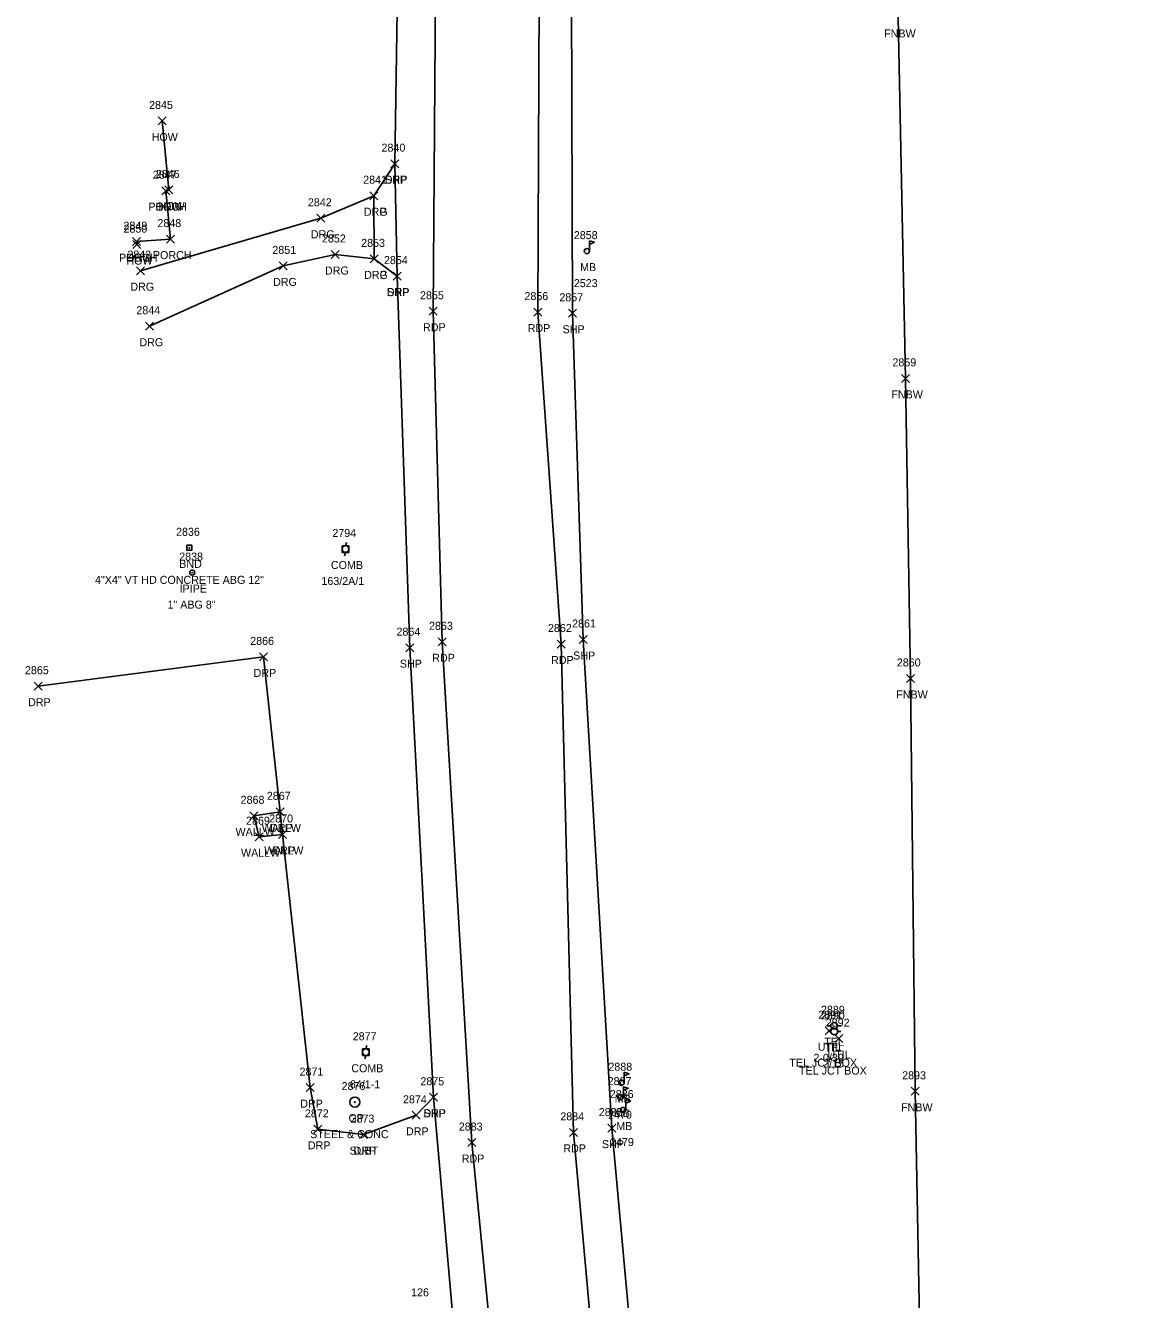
# Model space of a CAD drawing. Extents: x 1443071 to 1445292, y 614024 to 622563.
# Drawn here: x 1443923.5 to 1444198.2, y 619223.1 to 619541.5 of the extents above; entities that cross this region are included whole.
import ezdxf

# ---------------------------------------------------------------- set-up
doc = ezdxf.new("R2010")
doc.units = 0
for name, color, linetype in [('C_I', 7, 'Continuous'), ('L_A', 7, 'Continuous'), ('L_C', 7, 'Continuous'), ('L_I', 7, 'Continuous'), ('L_TIC', 7, 'Continuous'), ('LBC', 7, 'Continuous'), ('LBF', 7, 'Continuous'), ('LFNC', 7, 'Continuous'), ('LMB', 7, 'Continuous'), ('LW', 7, 'Continuous'), ('M_A', 7, 'Continuous'), ('M_C', 7, 'Continuous'), ('M_I', 7, 'Continuous'), ('MHBP', 7, 'Continuous'), ('MPIP', 7, 'Continuous'), ('P_A', 7, 'Continuous'), ('P_I', 7, 'Continuous'), ('P_TIC', 7, 'Continuous'), ('PET', 7, 'Continuous'), ('PSP', 7, 'Continuous'), ('R_A', 7, 'Continuous'), ('R_C', 7, 'Continuous'), ('R_I', 7, 'Continuous'), ('R_TIC', 7, 'Continuous'), ('RDG', 7, 'Continuous'), ('RDP', 7, 'Continuous'), ('RGP', 7, 'Continuous'), ('U_A', 7, 'Continuous'), ('U_C', 7, 'Continuous'), ('U_I', 7, 'Continuous'), ('U_TIC', 7, 'Continuous'), ('UDEFAULT', 7, 'Continuous'), ('UP', 7, 'Continuous')]:
    doc.layers.add(name, color=color, linetype=linetype)

msp = doc.modelspace()

# ---------------------------------------------------------------- linework, layer by layer
at = {"layer": 'L_TIC'}
for points in [[(1443956.63, 619516.62), (1443958.63, 619518.62)], [(1443958.63, 619516.62), (1443956.63, 619518.62)], [(1443957.56, 619499.19), (1443959.56, 619501.19)], [(1443959.56, 619499.19), (1443957.56, 619501.19)], [(1443957.56, 619499.19), (1443959.56, 619501.19)], [(1443959.56, 619499.19), (1443957.56, 619501.19)], [(1443958.34, 619499.37), (1443960.34, 619501.37)], [(1443960.34, 619499.37), (1443958.34, 619501.37)], [(1443950.24, 619486.45), (1443952.24, 619488.45)], [(1443952.24, 619486.45), (1443950.24, 619488.45)], [(1443950.24, 619486.45), (1443952.24, 619488.45)], [(1443952.24, 619486.45), (1443950.24, 619488.45)], [(1443950.31, 619485.7), (1443952.31, 619487.7)], [(1443952.31, 619485.7), (1443950.31, 619487.7)], [(1443958.71, 619487.09), (1443960.71, 619489.09)], [(1443960.71, 619487.09), (1443958.71, 619489.09)], [(1444142.47, 619452.28), (1444144.47, 619454.28)], [(1444144.47, 619452.28), (1444142.47, 619454.28)], [(1444143.69, 619377.28), (1444145.69, 619379.28)], [(1444145.69, 619377.28), (1444143.69, 619379.28)], [(1443979.56, 619342.95), (1443981.56, 619344.95)], [(1443981.56, 619342.95), (1443979.56, 619344.95)], [(1443986.11, 619343.95), (1443988.11, 619345.95)], [(1443988.11, 619343.95), (1443986.11, 619345.95)], [(1443980.93, 619337.73), (1443982.93, 619339.73)], [(1443982.93, 619337.73), (1443980.93, 619339.73)], [(1443986.74, 619338.29), (1443988.74, 619340.29)], [(1443988.74, 619338.29), (1443986.74, 619340.29)], [(1444144.89, 619274.11), (1444146.89, 619276.11)], [(1444146.89, 619274.11), (1444144.89, 619276.11)]]:
    msp.add_lwpolyline(points, dxfattribs=at)
at = {"layer": 'LBC'}
for points in [[(1443957.63, 619517.62), (1443959.34, 619500.37), (1443958.56, 619500.19)], [(1443951.24, 619487.45), (1443951.31, 619486.7)]]:
    msp.add_lwpolyline(points, dxfattribs=at)
at = {"layer": 'LBF'}
msp.add_lwpolyline([(1443958.56, 619500.19), (1443959.71, 619488.09), (1443951.24, 619487.45)], dxfattribs=at)
at = {"layer": 'LFNC'}
msp.add_lwpolyline([(1444140.95, 619617.62), (1444141.66, 619543.48), (1444143.47, 619453.28), (1444144.69, 619378.28), (1444145.89, 619275.11), (1444147.59, 619182.81), (1444151.11, 619052.76), (1444160.95, 618964.58), (1444173.83, 618850.02), (1444185.25, 618752.69), (1444198.22, 618656.01)], dxfattribs=at)
at = {"layer": 'LMB'}
for p, q in [((1444064.46, 619487.68), (1444065.76, 619487.3)), ((1444064.47, 619485.09), (1444064.47, 619487.68)), ((1444064.47, 619486.78), (1444065.75, 619487.29)), ((1444063.81, 619485.08), (1444063.81, 619485.08)), ((1444073.1, 619279.85), (1444074.4, 619279.47)), ((1444073.11, 619277.26), (1444073.11, 619279.85)), ((1444072.45, 619277.25), (1444072.45, 619277.25)), ((1444073.11, 619278.95), (1444074.39, 619279.46)), ((1444072.27, 619273.65), (1444072.27, 619273.65)), ((1444072.92, 619276.25), (1444074.22, 619275.86)), ((1444072.93, 619273.65), (1444072.93, 619276.25)), ((1444072.93, 619275.35), (1444074.21, 619275.86)), ((1444072.86, 619270.42), (1444072.86, 619270.42)), ((1444073.51, 619273.02), (1444074.81, 619272.63)), ((1444073.52, 619270.42), (1444073.52, 619273.02)), ((1444073.52, 619272.12), (1444074.8, 619272.63))]:
    msp.add_line(p, q, dxfattribs=at)
for centre in [(1444063.81, 619485.08), (1444072.45, 619277.25), (1444072.27, 619273.65), (1444072.86, 619270.42)]:
    msp.add_circle(centre, 0.656, dxfattribs=at)
at = {"layer": 'LW'}
msp.add_lwpolyline([(1443987.11, 619344.95), (1443980.56, 619343.95), (1443981.93, 619338.73), (1443987.74, 619339.29)], dxfattribs=at)
at = {"layer": 'MHBP'}
msp.add_lwpolyline([(1443963.8, 619411.56), (1443965.05, 619411.56), (1443965.05, 619410.31), (1443963.8, 619410.31)], close=True, dxfattribs=at)
msp.add_circle((1443964.42, 619410.93), 0.0833, dxfattribs=at)
at = {"layer": 'MPIP'}
for radius in [0.625, 0.0833]:
    msp.add_circle((1443965.16, 619404.74), radius, dxfattribs=at)
at = {"layer": 'P_TIC'}
for points in [[(1444014.83, 619505.94), (1444016.83, 619507.94)], [(1444016.83, 619505.94), (1444014.83, 619507.94)], [(1444015.35, 619477.84), (1444017.35, 619479.84)], [(1444017.35, 619477.84), (1444015.35, 619479.84)], [(1444024.36, 619469.06), (1444026.36, 619471.06)], [(1444026.36, 619469.06), (1444024.36, 619471.06)], [(1444050.53, 619468.84), (1444052.53, 619470.84)], [(1444052.53, 619468.84), (1444050.53, 619470.84)], [(1444059.2, 619468.56), (1444061.2, 619470.56)], [(1444061.2, 619468.56), (1444059.2, 619470.56)], [(1444026.67, 619386.44), (1444028.67, 619388.44)], [(1444028.67, 619386.44), (1444026.67, 619388.44)], [(1444061.86, 619387.02), (1444063.86, 619389.02)], [(1444063.86, 619387.02), (1444061.86, 619389.02)], [(1444018.52, 619384.97), (1444020.52, 619386.97)], [(1444020.52, 619384.97), (1444018.52, 619386.97)], [(1444056.39, 619385.89), (1444058.39, 619387.89)], [(1444058.39, 619385.89), (1444056.39, 619387.89)], [(1444024.45, 619272.62), (1444026.45, 619274.62)], [(1444026.45, 619272.62), (1444024.45, 619274.62)], [(1444059.43, 619263.84), (1444061.43, 619265.84)], [(1444061.43, 619263.84), (1444059.43, 619265.84)], [(1444069.04, 619264.9), (1444071.04, 619266.9)], [(1444071.04, 619264.9), (1444069.04, 619266.9)], [(1444034.05, 619261.29), (1444036.05, 619263.29)], [(1444036.05, 619261.29), (1444034.05, 619263.29)]]:
    msp.add_lwpolyline(points, dxfattribs=at)
at = {"layer": 'PET'}
for points in [[(1444060.23, 619757.24), (1444030.6, 619759.6), (1444027.22, 619690.19), (1444024.14, 619595.2), (1444026, 619550.02), (1444025.36, 619470.06), (1444027.67, 619387.44), (1444035.05, 619262.29), (1444046.36, 619146.08), (1444057.76, 619040.09), (1444068.86, 618946.58), (1444081.65, 618839.75), (1444094.51, 618740.27), (1444109.49, 618620.85), (1444119.47, 618545.62)], [(1444060.23, 619757.24), (1444055.7, 619686.84), (1444052.09, 619593.54), (1444051.88, 619548.79), (1444051.53, 619469.84), (1444057.39, 619386.89), (1444060.43, 619264.84), (1444070.47, 619153.76), (1444082.27, 619042.98), (1444093.27, 618950.3), (1444106.23, 618841.72), (1444119.2, 618742.75), (1444134.15, 618623.05), (1444144.16, 618546.64)]]:
    msp.add_lwpolyline(points, dxfattribs=at)
at = {"layer": 'PSP'}
for points in [[(1444030.6, 619759.6), (1444029.33, 619753.09), (1444025.71, 619690.24), (1444018.62, 619596.21), (1444016.49, 619550.78), (1444015.83, 619506.94), (1444016.35, 619478.84), (1444019.52, 619385.97), (1444025.45, 619273.62), (1444031.18, 619208.3), (1444036.73, 619143.63), (1444046.33, 619051.58), (1444050.41, 619020.07), (1444060.07, 618945.31), (1444073.2, 618838.48), (1444085.76, 618739.52), (1444101.61, 618620.44), (1444111.35, 618544.8)], [(1444060.23, 619757.24), (1444060.46, 619750.33), (1444058.96, 619686.98), (1444059.06, 619593.34), (1444060.01, 619548.92), (1444060.2, 619469.56), (1444062.86, 619388.02), (1444070.04, 619265.9), (1444080.12, 619155.61), (1444092.23, 619044.26), (1444103.72, 618951.36), (1444117.15, 618842.88), (1444129.88, 618744.38), (1444144.78, 618624.26), (1444154.69, 618549.98)]]:
    msp.add_lwpolyline(points, dxfattribs=at)
at = {"layer": 'R_TIC'}
for points in [[(1444014.83, 619505.94), (1444016.83, 619507.94)], [(1444016.83, 619505.94), (1444014.83, 619507.94)], [(1444009.58, 619497.93), (1444011.58, 619499.93)], [(1444011.58, 619497.93), (1444009.58, 619499.93)], [(1444009.58, 619497.93), (1444011.58, 619499.93)], [(1444011.58, 619497.93), (1444009.58, 619499.93)], [(1443996.33, 619492.29), (1443998.33, 619494.29)], [(1443998.33, 619492.29), (1443996.33, 619494.29)], [(1443999.85, 619483.24), (1444001.85, 619485.24)], [(1444001.85, 619483.24), (1443999.85, 619485.24)], [(1444009.65, 619482.15), (1444011.65, 619484.15)], [(1444011.65, 619482.15), (1444009.65, 619484.15)], [(1444009.65, 619482.15), (1444011.65, 619484.15)], [(1444011.65, 619482.15), (1444009.65, 619484.15)], [(1443951.2, 619479.2), (1443953.2, 619481.2)], [(1443953.2, 619479.2), (1443951.2, 619481.2)], [(1443986.89, 619480.39), (1443988.89, 619482.39)], [(1443988.89, 619480.39), (1443986.89, 619482.39)], [(1444015.35, 619477.84), (1444017.35, 619479.84)], [(1444017.35, 619477.84), (1444015.35, 619479.84)], [(1443953.45, 619465.32), (1443955.45, 619467.32)], [(1443955.45, 619465.32), (1443953.45, 619467.32)], [(1443982.01, 619382.67), (1443984.01, 619384.67)], [(1443984.01, 619382.67), (1443982.01, 619384.67)], [(1443925.64, 619375.35), (1443927.64, 619377.35)], [(1443927.64, 619375.35), (1443925.64, 619377.35)], [(1443986.11, 619343.95), (1443988.11, 619345.95)], [(1443988.11, 619343.95), (1443986.11, 619345.95)], [(1443986.74, 619338.29), (1443988.74, 619340.29)], [(1443988.74, 619338.29), (1443986.74, 619340.29)], [(1443993.67, 619275.02), (1443995.67, 619277.02)], [(1443995.67, 619275.02), (1443993.67, 619277.02)], [(1444024.45, 619272.62), (1444026.45, 619274.62)], [(1444026.45, 619272.62), (1444024.45, 619274.62)], [(1444020.1, 619268.1), (1444022.1, 619270.1)], [(1444022.1, 619268.1), (1444020.1, 619270.1)], [(1443995.58, 619264.6), (1443997.58, 619266.6)], [(1443997.58, 619264.6), (1443995.58, 619266.6)], [(1444007, 619263.28), (1444009, 619265.28)], [(1444009, 619263.28), (1444007, 619265.28)]]:
    msp.add_lwpolyline(points, dxfattribs=at)
at = {"layer": 'RDG'}
for points in [[(1444010.58, 619498.93), (1443997.33, 619493.29), (1443952.2, 619480.2)], [(1443954.45, 619466.32), (1443987.89, 619481.39), (1444000.85, 619484.24), (1444010.65, 619483.15)]]:
    msp.add_lwpolyline(points, dxfattribs=at)
at = {"layer": 'RDP'}
for points in [[(1444015.83, 619506.94), (1444010.58, 619498.93), (1444010.65, 619483.15), (1444016.35, 619478.84)], [(1443926.64, 619376.35), (1443983.01, 619383.67), (1443987.11, 619344.95), (1443987.74, 619339.29), (1443994.67, 619276.02), (1443996.58, 619265.6), (1444008, 619264.28), (1444021.1, 619269.1), (1444025.45, 619273.62)]]:
    msp.add_lwpolyline(points, dxfattribs=at)
at = {"layer": 'RGP'}
msp.add_line((1444005.81, 619272.4), (1444005.81, 619272.4), dxfattribs=at)
for radius in [1.25, 0.0833]:
    msp.add_circle((1444005.81, 619272.4), radius, dxfattribs=at)
at = {"layer": 'U_TIC'}
for points in [[(1444007, 619263.28), (1444009, 619265.28)], [(1444009, 619263.28), (1444007, 619265.28)]]:
    msp.add_lwpolyline(points, dxfattribs=at)
at = {"layer": 'UDEFAULT'}
for points in [[(1444123.35, 619289.25), (1444125.35, 619291.25)], [(1444125.35, 619289.25), (1444123.35, 619291.25)], [(1444125.79, 619287.27), (1444127.79, 619289.27)], [(1444127.79, 619287.27), (1444125.79, 619289.27)]]:
    msp.add_lwpolyline(points, dxfattribs=at)
at = {"layer": 'UP'}
for p, q in [((1444002.61, 619409.8), (1444002.61, 619411.47)), ((1444002.61, 619411.47), (1444004.28, 619411.47)), ((1444003.7, 619412.3), (1444003.45, 619411.47)), ((1444003.45, 619410.64), (1444003.45, 619410.64)), ((1444004.28, 619411.47), (1444004.28, 619409.8)), ((1444004.28, 619409.8), (1444002.61, 619409.8)), ((1444003.2, 619408.97), (1444003.45, 619409.8)), ((1444123.94, 619291.47), (1444124.76, 619291.47)), ((1444124.01, 619290.07), (1444124.83, 619290.07)), ((1444125.6, 619291.48), (1444125.6, 619291.48)), ((1444125.67, 619290.07), (1444125.67, 619290.07)), ((1444127.26, 619291.48), (1444126.43, 619291.48)), ((1444126.43, 619291.48), (1444126.43, 619291.48)), ((1444127.33, 619290.07), (1444126.5, 619290.07)), ((1444126.5, 619290.07), (1444126.5, 619290.07)), ((1444127.26, 619291.48), (1444127.26, 619291.48)), ((1444127.33, 619290.07), (1444127.33, 619290.07)), ((1444008.79, 619286.53), (1444008.54, 619285.7)), ((1444007.7, 619284.03), (1444007.7, 619285.7)), ((1444007.7, 619285.7), (1444009.37, 619285.7)), ((1444009.37, 619284.03), (1444007.7, 619284.03)), ((1444008.29, 619283.2), (1444008.54, 619284.03)), ((1444008.54, 619284.86), (1444008.54, 619284.86)), ((1444009.37, 619285.7), (1444009.37, 619284.03))]:
    msp.add_line(p, q, dxfattribs=at)
for centre in [(1444003.45, 619410.64), (1444125.6, 619291.48), (1444125.67, 619290.07), (1444008.54, 619284.86)]:
    msp.add_circle(centre, 0.833, dxfattribs=at)

# ---------------------------------------------------------------- texts
at = {"layer": 'C_I'}
msp.add_text('126', height=2, dxfattribs=at).set_placement((1444019.87, 619223.86))
at = {"layer": 'L_A'}
for s, p in [('FNBW', (1444138.13, 619538.48)), ('HOW', (1443955.02, 619512.62)), ('PORCH', (1443954.19, 619495.19)), ('HOW', (1443955.95, 619495.19)), ('HOW', (1443956.73, 619495.37)), ('PORCH', (1443946.86, 619482.45)), ('HOW', (1443948.62, 619482.45)), ('HOW', (1443948.7, 619481.7)), ('PORCH', (1443955.33, 619483.09)), ('MB', (1444062.12, 619480.08)), ('FNBW', (1444139.94, 619448.28)), ('FNBW', (1444141.16, 619373.28)), ('WALLW', (1443975.98, 619338.95)), ('WALLW', (1443982.53, 619339.95)), ('WALLW', (1443977.35, 619333.73)), ('WALLW', (1443983.16, 619334.29)), ('MB', (1444070.76, 619272.25)), ('MB', (1444070.58, 619268.65)), ('FNBW', (1444142.36, 619270.11)), ('MB', (1444071.17, 619265.42))]:
    msp.add_text(s, height=2, dxfattribs=at).set_placement(p)
at = {"layer": 'L_C'}
for s, p in [('2523', (1444060.55, 619476.08)), ('2470', (1444069.11, 619268.25)), ('2479', (1444069.6, 619261.42))]:
    msp.add_text(s, height=2, dxfattribs=at).set_placement(p)
at = {"layer": 'L_I'}
for s, p in [('2845', (1443954.37, 619520.62)), ('2847', (1443955.3, 619503.19)), ('2847', (1443955.3, 619503.19)), ('2846', (1443956.03, 619503.37)), ('2850', (1443947.97, 619489.7)), ('2849', (1443947.97, 619490.45)), ('2849', (1443947.97, 619490.45)), ('2848', (1443956.45, 619491.09)), ('2858', (1444060.55, 619488.08)), ('2859', (1444140.2, 619456.28)), ('2860', (1444141.3, 619381.28)), ('2867', (1443983.81, 619347.95)), ('2868', (1443977.26, 619346.95)), ('2869', (1443978.62, 619341.73)), ('2870', (1443984.4, 619342.29)), ('2888', (1444069.19, 619280.25)), ('2893', (1444142.63, 619278.11)), ('2887', (1444069.01, 619276.65)), ('2886', (1444069.55, 619273.42))]:
    msp.add_text(s, height=2, dxfattribs=at).set_placement(p)
at = {"layer": 'M_A'}
for s, p in [('BND', (1443961.91, 619405.93)), ('IPIPE', (1443961.99, 619399.74))]:
    msp.add_text(s, height=2, dxfattribs=at).set_placement(p)
at = {"layer": 'M_C'}
for s, p in [('4"X4" VT HD CONCRETE ABG 12"', (1443940.86, 619401.93)), ('1" ABG 8"', (1443958.98, 619395.74))]:
    msp.add_text(s, height=2, dxfattribs=at).set_placement(p)
at = {"layer": 'M_I'}
for s, p in [('2836', (1443961.11, 619413.93)), ('2838', (1443961.9, 619407.74))]:
    msp.add_text(s, height=2, dxfattribs=at).set_placement(p)
at = {"layer": 'P_A'}
for s, p in [('SHP', (1444013.36, 619501.94)), ('SHP', (1444013.88, 619473.84)), ('RDP', (1444022.85, 619465.06)), ('RDP', (1444049.02, 619464.84)), ('SHP', (1444057.74, 619464.56)), ('SHP', (1444060.39, 619383.02)), ('SHP', (1444017.06, 619380.97)), ('RDP', (1444025.16, 619382.44)), ('RDP', (1444054.87, 619381.89)), ('SHP', (1444022.99, 619268.62)), ('RDP', (1444057.92, 619259.84)), ('SHP', (1444067.57, 619260.9)), ('RDP', (1444032.54, 619257.29))]:
    msp.add_text(s, height=2, dxfattribs=at).set_placement(p)
at = {"layer": 'P_I'}
for s, p in [('2840', (1444012.48, 619509.94)), ('2854', (1444013.09, 619481.84)), ('2855', (1444022.1, 619473.06)), ('2856', (1444048.21, 619472.84)), ('2857', (1444056.94, 619472.56)), ('2863', (1444024.36, 619390.44)), ('2862', (1444054.08, 619389.89)), ('2861', (1444060.12, 619391.02)), ('2864', (1444016.22, 619388.97)), ('2875', (1444022.19, 619276.62)), ('2885', (1444066.78, 619268.9)), ('2883', (1444031.8, 619265.29)), ('2884', (1444057.17, 619267.84))]:
    msp.add_text(s, height=2, dxfattribs=at).set_placement(p)
at = {"layer": 'R_A'}
for s, p in [('DRP', (1444013.31, 619501.94)), ('DRG', (1444008.07, 619493.93)), ('DRP', (1444008.07, 619493.93)), ('DRG', (1443994.82, 619488.29)), ('DRG', (1443998.34, 619479.24)), ('DRG', (1443985.37, 619476.39)), ('DRG', (1444008.14, 619478.15)), ('DRP', (1444008.14, 619478.15)), ('DRG', (1443949.69, 619475.2)), ('DRP', (1444013.83, 619473.84)), ('DRG', (1443951.94, 619461.32)), ('DRP', (1443980.5, 619378.67)), ('DRP', (1443924.13, 619371.35)), ('DRP', (1443984.6, 619339.95)), ('DRP', (1443985.23, 619334.29)), ('DRP', (1443992.16, 619271.02)), ('DRP', (1444022.94, 619268.62)), ('GP', (1444004.24, 619267.4)), ('DRP', (1444018.59, 619264.1)), ('DRP', (1443994.06, 619260.6)), ('DRP', (1444005.49, 619259.28))]:
    msp.add_text(s, height=2, dxfattribs=at).set_placement(p)
at = {"layer": 'R_C'}
msp.add_text('STEEL & CONC', height=2, dxfattribs=at).set_placement((1443994.64, 619263.4))
at = {"layer": 'R_I'}
for s, p in [('2840', (1444012.48, 619509.94)), ('2841', (1444007.89, 619501.93)), ('2841', (1444007.89, 619501.93)), ('2842', (1443994.07, 619496.29)), ('2852', (1443997.59, 619487.24)), ('2853', (1444007.39, 619486.15)), ('2853', (1444007.39, 619486.15)), ('2843', (1443948.94, 619483.2)), ('2851', (1443985.19, 619484.39)), ('2854', (1444013.09, 619481.84)), ('2844', (1443951.19, 619469.32)), ('2866', (1443979.65, 619386.67)), ('2865', (1443923.34, 619379.35)), ('2867', (1443983.81, 619347.95)), ('2870', (1443984.4, 619342.29)), ('2871', (1443991.98, 619279.02)), ('2876', (1444002.5, 619275.4)), ('2875', (1444022.19, 619276.62)), ('2874', (1444017.84, 619272.1)), ('2872', (1443993.32, 619268.6)), ('2873', (1444004.74, 619267.28))]:
    msp.add_text(s, height=2, dxfattribs=at).set_placement(p)
at = {"layer": 'U_A'}
for s, p in [('COMB', (1443999.83, 619405.64)), ('UTIL', (1444121.52, 619285.25)), ('TEL', (1444123.16, 619286.48)), ('TEL', (1444123.23, 619285.07)), ('UTIL', (1444123.95, 619283.27)), ('COMB', (1444004.92, 619279.86)), ('SUBT', (1444004.49, 619259.28))]:
    msp.add_text(s, height=2, dxfattribs=at).set_placement(p)
at = {"layer": 'U_C'}
for s, p in [('163/2A/1', (1443997.45, 619401.64)), ('TEL JCT BOX', (1444114.42, 619281.25)), ('2-0/39', (1444120.45, 619282.48)), ('2/15', (1444122.89, 619281.07)), ('TEL JCT BOX', (1444116.85, 619279.27)), ('64/1-1', (1444004.57, 619275.86))]:
    msp.add_text(s, height=2, dxfattribs=at).set_placement(p)
at = {"layer": 'U_I'}
for s, p in [('2794', (1444000.19, 619413.64)), ('2889', (1444122.33, 619294.48)), ('2891', (1444121.66, 619293.25)), ('2890', (1444122.32, 619293.07)), ('2892', (1444123.53, 619291.27)), ('2877', (1444005.28, 619287.86)), ('2873', (1444004.74, 619267.28))]:
    msp.add_text(s, height=2, dxfattribs=at).set_placement(p)

doc.saveas('drawing.dxf')
